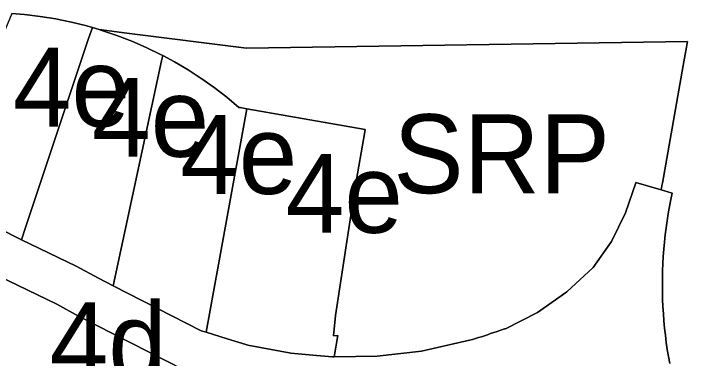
# Model space of a CAD drawing. Extents: x 598968 to 613553, y 4409678 to 4430833.
# Drawn here: x 609932.9 to 610035.5, y 4416559.5 to 4416612 of the extents above; entities that cross this region are included whole.
import ezdxf

# ---------------------------------------------------------------- set-up
doc = ezdxf.new("R2010")
doc.units = 0
for name, color, linetype in [('1', 7, 'Continuous'), ('4d. Sector de consolidació - ANNEX III A', 7, 'Continuous'), ('4e. Sector de consolidació - ANNEX III A', 7, 'Continuous'), ('Sòl Rústic Protegit', 7, 'Continuous'), ('Sòl Rústic Protegit - Alt Nivell de Protecció', 7, 'Continuous')]:
    doc.layers.add(name, color=color, linetype=linetype)

msp = doc.modelspace()

# ---------------------------------------------------------------- linework, layer by layer
at = {"layer": '1'}
for points in [[(610032.8224, 4416558.7389), (610032.6306, 4416559.8139), (610032.4567, 4416560.892), (610032.3008, 4416561.9727), (610032.1629, 4416563.056), (610032.043, 4416564.1414), (610031.9412, 4416565.2286), (610031.8575, 4416566.3173), (610031.7919, 4416567.4074), (610031.7445, 4416568.4983), (610031.7152, 4416569.5899), (610031.704, 4416570.6818), (610031.7111, 4416571.7738), (610031.7363, 4416572.8655), (610031.7796, 4416573.9566), (610031.841, 4416575.0469), (610031.9206, 4416576.1359), (610032.0184, 4416577.2235), (610032.1342, 4416578.3094), (610032.268, 4416579.3931), (610032.4199, 4416580.4745), (610032.5896, 4416581.5532), (610032.7774, 4416582.6289), (610032.983, 4416583.7014), (610033.1909, 4416584.6961), (610031.5221, 4416585.1752), (610027.6513, 4416586.2863), (610027.6397, 4416586.2437), (610026.1093, 4416581.6593), (610023.9366, 4416577.342), (610021.1667, 4416573.3814), (610017.1571, 4416569.6631), (610012.674, 4416566.532), (610007.8027, 4416564.0476), (610007.6576, 4416564.0039), (610007.0964, 4416563.8242), (610006.5582, 4416563.6441), (610006.0436, 4416563.4672), (610005.5497, 4416563.2957), (610005.0738, 4416563.131), (610004.6132, 4416562.9747), (610004.1654, 4416562.8275), (610003.7256, 4416562.6895), (610003.2807, 4416562.5579), (610002.8201, 4416562.4297), (610002.3428, 4416562.3047), (610001.7079, 4416562.1484), (609995.0591, 4416560.6537), (609988.2909, 4416559.8585), (609981.7565, 4416559.7752), (609981.615, 4416559.7734), (609981.4767, 4416559.7716), (609979.0385, 4416559.9951), (609975.1375, 4416560.3309), (609974.9139, 4416560.3733), (609972.1268, 4416560.9017), (609968.6128, 4416561.568), (609968.3101, 4416561.658), (609965.4711, 4416562.5019), (609962.2537, 4416563.4964), (609961.495, 4416563.731), (609948.1193, 4416570.5685), (609945.8469, 4416571.7301), (609942.4738, 4416573.5587), (609934.1257, 4416577.5903), (609933.3448, 4416577.9674), (609920.6647, 4416584.4869)], [(609930.5284, 4416572.1129), (609939.5099, 4416567.7717), (609942.8183, 4416565.9783), (609958.8775, 4416557.7689)]]:
    msp.add_lwpolyline(points, dxfattribs=at)
at = {"layer": '4d. Sector de consolidació - ANNEX III A'}
msp.add_lwpolyline([(609958.8775, 4416557.7689), (609942.8183, 4416565.9783), (609939.5099, 4416567.7717), (609930.5284, 4416572.1129), (609927.8768, 4416572.2512), (609925.2352, 4416571.983), (609922.6654, 4416571.315), (609920.2277, 4416570.2626), (609917.9793, 4416568.8505), (609924.9648, 4416547.5038), (609931.5149, 4416543.7771), (609932.7742, 4416543.0756), (609939.1987, 4416539.8547), (609946.3385, 4416542.2232), (609950.8213, 4416541.1964)], close=True, dxfattribs=at)
at = {"layer": '4e. Sector de consolidació - ANNEX III A'}
for points in [[(609944.9717, 4416609.8555), (609944.079, 4416610.1172), (609941.742, 4416610.6986), (609940.0334, 4416611.0495), (609939.383, 4416611.1831), (609937.0062, 4416611.5698), (609934.6154, 4416611.8582), (609932.6569, 4416612.0127), (609931.6897, 4416609.6894), (609920.6647, 4416584.4869), (609933.3448, 4416577.9674), (609934.1257, 4416577.5903), (609934.7413, 4416579.4366), (609944.3314, 4416608.1999)], [(609945.9535, 4416609.5677), (609944.9717, 4416609.8555), (609944.3314, 4416608.1999), (609934.7413, 4416579.4366), (609934.1257, 4416577.5903), (609942.4738, 4416573.5587), (609945.8469, 4416571.7301), (609948.1193, 4416570.5685), (609955.4725, 4416604.793), (609955.6368, 4416605.6142), (609955.2958, 4416605.7967), (609953.1277, 4416606.8446), (609950.9181, 4416607.8021), (609948.6708, 4416608.6677), (609946.3898, 4416609.4398)], [(609968.4539, 4416597.5089), (609967.4135, 4416597.6909), (609967.2347, 4416597.7222), (609965.3895, 4416599.2696), (609963.4821, 4416600.7395), (609962.4734, 4416601.4524), (609961.7394, 4416601.9712), (609961.5155, 4416602.1295), (609959.4933, 4416603.4371), (609957.419, 4416604.6602), (609955.6368, 4416605.6142), (609955.4725, 4416604.793), (609948.1193, 4416570.5685), (609961.495, 4416563.731), (609962.2537, 4416563.4964)], [(609981.7565, 4416559.7752), (609982.304, 4416563.0017), (609981.6338, 4416562.9682), (609981.93, 4416566.0482), (609984.9599, 4416585.6078), (609986.413, 4416594.0291), (609986.4697, 4416594.3576), (609968.4539, 4416597.5089), (609962.2537, 4416563.4964), (609965.4711, 4416562.5019), (609968.3101, 4416561.658), (609968.6128, 4416561.568), (609972.1268, 4416560.9017), (609974.9139, 4416560.3733), (609975.1375, 4416560.3309), (609979.0385, 4416559.9951), (609981.4767, 4416559.7716), (609981.615, 4416559.7734)]]:
    msp.add_lwpolyline(points, close=True, dxfattribs=at)
at = {"layer": 'Sòl Rústic Protegit'}
msp.add_lwpolyline([(610031.5221, 4416585.1752), (610031.6873, 4416586.086), (610031.7197, 4416586.2004), (610034.8941, 4416604.1014), (610035.3893, 4416606.8936), (610035.4977, 4416607.5044), (610035.5323, 4416607.7004), (610035.5199, 4416607.7002), (610035.5267, 4416607.7394), (609968.4025, 4416606.7382), (609950.1693, 4416609.0364), (609945.9535, 4416609.5677), (609946.3898, 4416609.4398), (609948.6708, 4416608.6677), (609950.9181, 4416607.8021), (609953.1277, 4416606.8446), (609955.2958, 4416605.7967), (609955.6368, 4416605.6142), (609957.419, 4416604.6602), (609959.4933, 4416603.4371), (609961.5155, 4416602.1295), (609961.7394, 4416601.9712), (609962.4734, 4416601.4524), (609963.4821, 4416600.7395), (609965.3895, 4416599.2696), (609967.2347, 4416597.7222), (609967.4135, 4416597.6909), (609968.4539, 4416597.5089), (609986.4697, 4416594.3576), (609986.413, 4416594.0291), (609984.9599, 4416585.6078), (609981.93, 4416566.0482), (609981.6338, 4416562.9682), (609982.304, 4416563.0017), (609981.7565, 4416559.7752), (609988.2909, 4416559.8585), (609995.0591, 4416560.6537), (610001.7079, 4416562.1484), (610002.3428, 4416562.3047), (610002.8201, 4416562.4297), (610003.2807, 4416562.5579), (610003.7256, 4416562.6895), (610004.1654, 4416562.8275), (610004.6132, 4416562.9747), (610005.0738, 4416563.131), (610005.5497, 4416563.2957), (610006.0436, 4416563.4672), (610006.5582, 4416563.6441), (610007.0964, 4416563.8242), (610007.6576, 4416564.0039), (610007.8027, 4416564.0476), (610012.674, 4416566.532), (610017.1571, 4416569.6631), (610021.1667, 4416573.3814), (610023.9366, 4416577.342), (610026.1093, 4416581.6593), (610027.6397, 4416586.2437), (610027.6513, 4416586.2863)], close=True, dxfattribs=at)
at = {"layer": 'Sòl Rústic Protegit - Alt Nivell de Protecció'}
msp.add_lwpolyline([(609932.6569, 4416612.0127), (609934.6154, 4416611.8582), (609937.0062, 4416611.5698), (609939.383, 4416611.1831), (609940.0334, 4416611.0495), (609941.742, 4416610.6986), (609944.079, 4416610.1172), (609944.9717, 4416609.8555), (609945.9535, 4416609.5677), (609950.1693, 4416609.0364), (609968.4025, 4416606.7382), (610035.5267, 4416607.7394), (610035.5199, 4416607.7002), (610035.5323, 4416607.7004), (610035.4977, 4416607.5044), (610035.3893, 4416606.8936), (610034.8941, 4416604.1014), (610031.7197, 4416586.2004), (610031.6873, 4416586.086), (610031.5221, 4416585.1752), (610033.1909, 4416584.6961), (610032.983, 4416583.7014), (610032.7774, 4416582.6289), (610032.5896, 4416581.5532), (610032.4199, 4416580.4745), (610032.268, 4416579.3931), (610032.1342, 4416578.3094), (610032.0184, 4416577.2235), (610031.9206, 4416576.1359), (610031.841, 4416575.0469), (610031.7796, 4416573.9566), (610031.7363, 4416572.8655), (610031.7111, 4416571.7738), (610031.704, 4416570.6818), (610031.7152, 4416569.5899), (610031.7445, 4416568.4983), (610031.7919, 4416567.4074), (610031.8575, 4416566.3173), (610031.9412, 4416565.2286), (610032.043, 4416564.1414), (610032.1629, 4416563.056), (610032.3008, 4416561.9727), (610032.4567, 4416560.892), (610032.6306, 4416559.8139), (610032.8224, 4416558.7389)], dxfattribs=at)

# ---------------------------------------------------------------- texts
at = {"layer": '4d. Sector de consolidació - ANNEX III A'}
msp.add_text('4d', height=12, dxfattribs=at).set_placement((609938.4284, 4416556.0529))
at = {"layer": '4e. Sector de consolidació - ANNEX III A'}
for p in [(609932.8182, 4416594.8015), (609944.8813, 4416590.212), (609958.2866, 4416584.5553), (609974.3617, 4416578.6403)]:
    msp.add_text('4e', height=12, dxfattribs=at).set_placement(p)
at = {"layer": 'Sòl Rústic Protegit'}
msp.add_text('SRP', height=12, dxfattribs=at).set_placement((609990.7429, 4416584.6715))

doc.saveas('drawing.dxf')
